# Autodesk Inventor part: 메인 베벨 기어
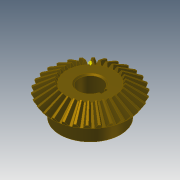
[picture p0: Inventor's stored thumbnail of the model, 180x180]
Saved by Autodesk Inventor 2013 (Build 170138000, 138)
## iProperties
Created: 2014-10
Part Number: 메인 베벨 기어
Material: Steel, Mild
Document SubType Name: Modeling
Designer: KYOUNG IL JANG
Categories: <?xml version="1.0" encoding="UTF-16"?> <MemberInstance><Categories><FamilyTemplate><FamilyTemplateParameter ValueType="xs:double" Id="1" ObjectReferenceKey="da
Mass: 269.583 g
Surface Area: 108.837 cm^2
Volume: 34.2981 cm^3
Density: 7.86 g/cm^3
CustomPartVersion: 1
Company: 한국ATC센터
Author: KYOUNG IL JANG
Revision Number: 1
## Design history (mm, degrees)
node "맨 위 점"
node "메쉬 평면2"
sketch "톱니 본체 스케치"
  geometry: L1 (0, 0)-(28.669, -21.997); L2 (28.669, -21.997)-(31.109, -18.336); L3 (31.109, -18.336)-(0, 0); L4 (30, -20)-(0, 0); L5 (17.219, -13.212)-(18.685, -11.013); L6 (28.669, -21.997)-(17.219, -13.212); L7 (31.109, -18.336)-(18.685, -11.013); L8 (0, -39.387)-(0, 6.564) reference; L9 (0, -20)-(31.109, -20)
  constraints: 16 end point, 4 point on line, 3 perpendicular, 2 collinear, 1 horizontal alignment, 1 vertical alignment
  dimensions: "d0" = 60 diameter of L4.start L8 (= da_de); "d1" = 57.33744 diameter of L1.end L8 (= da_dfe); "d2" = 62.2188 diameter of L2.end L8 (= da_dae); "d3" = 14.4 distance between parallel lines of L2 L5 (= da_b); "d4" = 18.3359 vertical distance of L2.end L1.start (= da_ve)
revolve "톱니 본체" sketch "톱니 본체 스케치" stored, may be unused: angle "d5" = 90 deg
node "시작점"
node "톱니 평면"
sketch "시작 스케치"
  geometry: L1 (0, -23.505)-(0, 10.645) reference; L2 (-0.709, -2.928)-(0.709, -2.928); A1 r 19.188 centre (-19.457, -7.014) between (-0.709, -2.928) and (-3.232, 3.229); A2 r 19.188 centre (19.457, -7.014) between (3.232, 3.229) and (0.709, -2.928); A3 r 57.403 centre (0, -54.083) between (3.232, 3.229) and (-3.232, 3.229); 1 further point
  constraints: 6 point on circle, 3 centre point, 3 symmetric about line, 2 end point, 1 coincident, 1 perpendicular, 1 other
  dimensions: "d7" = 19.18795 radius of A1 (= fd_rr); "d8" = 19.45712 horizontal distance of point (0, -54.083) A1.centre (= fd_x); "d9" = 47.06905 vertical distance of point (0, -54.083) A1.centre (= fd_y); "d57" = 57.40327 radius of A3 (= 0.5 x fd_dva + 0.3 x da_he); "d58" = 51.15527 distance from line of A3.centre L2 (= 0.5 x fd_dva - 1.12 x da_he)
node "끝점"
  node "끝 평면"
sketch "3D 스케치 오른쪽"
  node "Helical Curve Right" dims "d65" = 229.90621 (computed from da_dm, da_delta, da_beta), "d66" = 31.5, "d67" = 60 (= da_de), "d68" = -9.82794 (= -da_delta), "d69" = 8.10972 (computed from fd_loft, da_delta)
node "끝 평면 오른쪽"
sketch "끝 스케치 오른쪽"
  geometry: L1 (0, -41.54)-(0, 13.178) reference; L2 (-0.422, -1.69)-(0.422, -1.69); A1 r 11.427 centre (-11.587, -4.123) between (-0.422, -1.69) and (-1.925, 1.977); A2 r 11.427 centre (11.587, -4.123) between (1.925, 1.977) and (0.422, -1.69); A3 r 34.184 centre (0, -32.153) between (1.925, 1.977) and (-1.925, 1.977); 1 further point
  constraints: 6 point on circle, 3 centre point, 3 symmetric about line, 2 end point, 1 coincident, 1 perpendicular, 1 other
  dimensions: "d70" = 11.58699 horizontal distance of A3.centre A1.centre (computed from fd_x, fd_ratio); "d71" = 28.03028 vertical distance of point (0, -32.153) A1.centre (computed from fd_y, fd_ratio); "d72" = 11.4267 radius of A1 (computed from fd_rr, fd_ratio); "d73" = 30.46369 distance from line of point (0, -32.153) L2 (computed from d58, fd_ratio); "d74" = 34.18446 radius of A3 (computed from d57, fd_ratio)
feature "로프트 오른쪽" sketch "끝 스케치 오른쪽" dims "d75" = 0, "d77" = 0, "d79" = 0, "d80" = 90 deg, "d85" = 20, "d92" = 90 deg, "d93" = 90 deg, "da_teethtype" = 0 [user parameter]
sketch "3D 스케치 왼쪽"
  node "Helical Curve Left" dims "d26" = 229.90621 (computed from da_dm, da_delta, da_beta), "d27" = 8.10972 (computed from fd_loft, da_delta), "d28" = 60 (= da_de), "d29" = -9.82794 (= -da_delta)
node "끝 평면 왼쪽"
sketch "끝 스케치 왼쪽" dims "d56" = 10.3728 (derived)
  geometry: L1 (0, -43.753)-(0, 15.405) reference; L2 (-0.422, -1.678)-(0.422, -1.678); A1 r 11.427 centre (-11.587, -4.111) between (-0.422, -1.678) and (-1.925, 1.988); A2 r 11.427 centre (11.587, -4.111) between (1.925, 1.988) and (0.422, -1.678); A3 r 34.184 centre (0, -32.142) between (1.925, 1.988) and (-1.925, 1.988); 2 further points; 1 other entity
  constraints: 6 point on circle, 3 centre point, 3 symmetric about line, 2 end point, 1 coincident, 2 other
  dimensions: "d30" = 11.4267 radius of A1 (computed from fd_rr, fd_ratio); "d31" = 11.58699 horizontal distance of point (0, -32.142) A1.centre (computed from fd_x, fd_ratio); "d32" = 28.03028 vertical distance of A1.centre point (0, -32.142) (computed from fd_y, fd_ratio); "d61" = 34.18446 radius of A3 (computed from d57, fd_ratio); "d62" = 30.46369 distance from line of point (0, -32.142) L2 (computed from d58, fd_ratio)
feature "로프트 왼쪽" sketch "끝 스케치 왼쪽" dims "d35" = 0, "d37" = 0, "d39" = 0, "d40" = 90 deg, "d84" = 10, "d90" = 90 deg, "d91" = 90 deg, "da_teethtype" = 0 [user parameter]
sketch "본체 스케치"
  geometry: L1 (0, -35.038)-(0, -19.531) reference; L2 (28.669, -21.997)-(17.219, -13.212) reference; L3 (17.219, -13.212)-(0, -13.212); L4 (28.669, -21.997)-(0, -21.997)
  constraints: 4 end point, 2 perpendicular, 2 point on line
revolve "본체 고정" sketch "본체 스케치" stored, may be unused: angle "d46" = 90 deg
feature "피치 지름" dims angle "d47" = 90 deg
sketch "스케치8"
  geometry: C1 r 22.5 at (0, 0); 1 further point
  constraints: 1 centre point, 1 coincident
  dimensions: "d94" = 45 diameter of C1
extrude "돌출1" join sketch "스케치8" distance "d95" = 13; taper "d96" = 0 deg
sketch "스케치9"
  geometry: 1 further point
hole "구멍1" sketch "스케치9" at (0, 0) diameter "d97" = 17; stored, may be unused: countersink angle "d101" = 90 deg, drill point angle "d103" = 118 deg; dims "d98" = 6, "d99" = 4, "d100" = 2, "d102" = 8
sketch "스케치10"
  geometry: L1 (8.124, 2.5)-(10.8, 2.5); L2 (10.8, 2.5)-(10.8, -2.5); L3 (10.8, -2.5)-(8.124, -2.5); A1 r 8.5 centre (0, 0) between (8.124, 2.5) and (8.124, -2.5) reference; 1 further point
  constraints: 6 end point, 2 parallel, 2 point on circle, 1 horizontal, 1 perpendicular
  dimensions: "d104" = 5 distance of L1.end L2.end; "d112" = 19.3 dimension on A1 L2
extrude "돌출2" cut sketch "스케치10" stored distance "d106" = 10; taper "d107" = 0 deg
chamfer "모따기1" distance "d108" = 1; stored, may be unused: second distance "d109" = 2, angle "d110" = 45 deg
fillet "모깎기1" dims "d111" = 2
body "Solid1"
feature "로프트" dims "d17" = 0, "d18" = 90 deg, "d19" = 0, "d20" = 90 deg, "d89" = 0, "da_teethtype" = 0 [user parameter]
pattern_circular "원형 패턴" dims angle "d22" = 360 deg, "d88" = 0, "da_teethtype" = 0 [user parameter]
pattern_circular "원형 패턴 오른쪽" dims angle "d82" = 360 deg, "da_teethtype" = 0 [user parameter]
pattern_circular "원형 패턴 왼쪽" dims angle "d42" = 360 deg, "da_teethtype" = 0 [user parameter]
sketch "끝 스케치"
  geometry: L1 (0, -15.359)-(0, 6.983) reference; L2 (-0.422, -1.69)-(0.422, -1.69); A1 r 11.427 centre (-11.587, -4.123) between (-0.422, -1.69) and (-1.925, 1.977); A2 r 11.427 centre (11.587, -4.123) between (1.925, 1.977) and (0.422, -1.69); A3 r 34.184 centre (0, -32.153) between (1.925, 1.977) and (-1.925, 1.977); 1 further point
  constraints: 6 point on circle, 3 centre point, 3 symmetric about line, 2 end point, 1 coincident, 1 other
  dimensions: "d12" = 11.4267 radius of A1 (computed from fd_rr, fd_ratio); "d15" = 11.58699 horizontal distance of A1.centre point (0, -32.153) (computed from fd_x, fd_ratio); "d16" = 28.03028 vertical distance of A1.centre point (0, -32.153) (computed from fd_y, fd_ratio); "d59" = 34.18446 radius of A3 (computed from d57, fd_ratio); "d60" = 30.46369 distance from line of A3.centre L2 (computed from d58, fd_ratio)
sketch "Sketch6"
  geometry: L1 (30, -20)-(0, 0) reference; L2 (0, -37.8)-(0, 6.3) reference
body "Srf1"
other parameters: "da_b" = 14.4 [user parameter; used in 2 equation terms], "da_de" = 60 [user parameter; used in 4 equation terms], "da_dae" = 62.2188 [user parameter; used in 2 equation terms], "da_dfe" = 57.33744 [user parameter; used in 1 equation term], "da_le" = 36.05551 [user parameter; used in 1 equation term], "da_omega" = 90 deg [user parameter; used in 1 equation term], "da_beta" = 0 [user parameter; used in 2 equation terms], "da_delta" = 9.82794 [user parameter; used in 8 equation terms], "da_alpha" = 20 deg [user parameter; used in 2 equation terms], "da_he" = 4.4 [user parameter; used in 4 equation terms], "da_ve" = 18.3359 [user parameter; used in 1 equation term], "fd_dv" = 108.16654 (computed from da_de, da_delta) [user parameter; used in 1 equation term], "fd_dva" = 112.16654 (computed from da_dae, da_delta) [user parameter; used in 3 equation terms], "fd_dvb" = 101.6433 (computed from fd_dv, da_alpha) [user parameter; used in 2 equation terms], "da_zv" = 540.83269 [user parameter; used in 1 equation term], "fd_loft" = 14.62 (= da_b + 0.05 x da_he) [user parameter; used in 4 equation terms], "fd_ratio" = 5.95514 (computed from da_le, fd_loft) [user parameter; used in 15 equation terms], "fd_rr" = 19.18795 (computed from fd_dd, fd_dvb) [user parameter; used in 6 equation terms], "fd_angle" = 0.29367 (computed from da_zv) [user parameter; used in 4 equation terms], "fd_x1" = 1.58802 (computed from da_dvw, fd_angle) [user parameter; used in 1 equation term], "fd_y1" = 54.05995 (computed from da_dvw, fd_angle) [user parameter; used in 1 equation term], "fd_x2" = 17.8691 (computed from fd_rr, fd_angle2, fd_angle) [user parameter; used in 1 equation term], "fd_y2" = 6.9909 (computed from fd_rr, fd_angle2, fd_angle) [user parameter; used in 1 equation term], "fd_x" = 19.45712 (= fd_x1 + fd_x2) [user parameter; used in 4 equation terms], "fd_y" = 47.06905 (= fd_y1 - fd_y2) [user parameter; used in 4 equation terms], "fd_angle2" = 3.43555 (computed from fd_dvb, fd_dd, da_alpha) [user parameter; used in 2 equation terms], "fd_dd" = 108.64654 (= fd_dva - 0.8 x da_he) [user parameter; used in 2 equation terms], "da_dvw" = 108.16654 [user parameter; used in 2 equation terms], "d11" = 14.62 (= fd_loft), "da_dm" = 48.01848 [user parameter; used in 2 equation terms], "da_x" = 0 [user parameter], "da_m" = 2 [user parameter], "d48" = 0, "d49" = 0, "d50" = 90 deg (= da_omega), "d51" = 6 deg (computed from da_z), "d52" = 0, "d53" = 0, "d54" = 0
